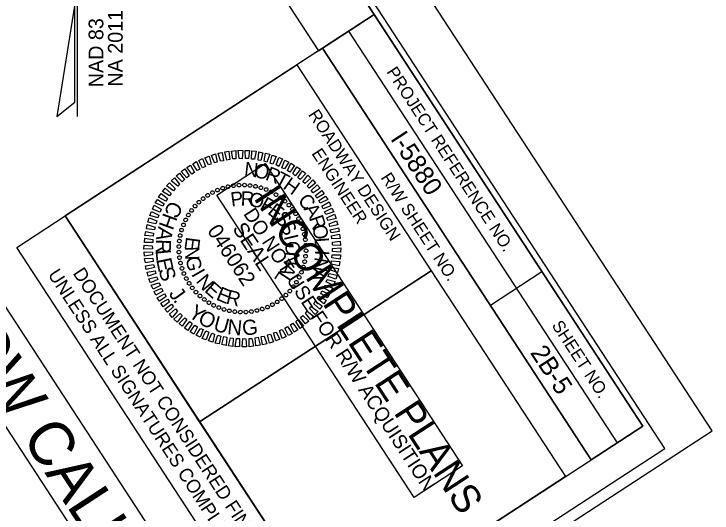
# Model space of a CAD drawing. Extents: x 1639622 to 2864602, y 842655 to 973236.
# Drawn here: x 1641174.9 to 1641458.9, y 843219.7 to 843422.9 of the extents above; entities that cross this region are included whole.
import ezdxf

# ---------------------------------------------------------------- set-up
doc = ezdxf.new("R2010")
doc.units = 0
for name, color, linetype in [('Default', 7, 'Continuous'), ('Old_Level_2', 7, 'Continuous'), ('Prop Dimension Text', 7, 'Continuous'), ('Prop DSN White Annotation Label', 7, 'Continuous'), ('Sheet Data Field CELL', 7, 'Continuous'), ('Sheet North Arrow CELL', 7, 'Continuous'), ('Sheet Plan CELL', 7, 'Continuous'), ('Sheet Plot Border Inside CELL', 7, 'Continuous'), ('Sheet Plot Border Outside CELL', 7, 'Continuous'), ('Sheet Sticker Exception Certification CELL', 7, 'Continuous'), ('Sheet Sticker Incomplete CELL', 7, 'Continuous')]:
    doc.layers.add(name, color=color, linetype=linetype)

msp = doc.modelspace()

# ---------------------------------------------------------------- linework, layer by layer
at = {"layer": 'Old_Level_2'}
for p, q in [((1641266.39, 843353.27), (1641266.39, 843353.27)), ((1641268.65, 843353.24), (1641268.65, 843353.24)), ((1641257.66, 843351.15), (1641257.66, 843351.15)), ((1641259.71, 843351.98), (1641259.71, 843351.98)), ((1641261.91, 843352.6), (1641261.91, 843352.6)), ((1641264.14, 843352.99), (1641264.14, 843352.99)), ((1641270.93, 843353.1), (1641270.93, 843353.1)), ((1641273.12, 843352.72), (1641273.12, 843352.72)), ((1641275.35, 843352.17), (1641275.35, 843352.17)), ((1641277.43, 843351.4), (1641277.43, 843351.4)), ((1641279.52, 843350.45), (1641279.52, 843350.45)), ((1641251.81, 843347.75), (1641251.81, 843347.75)), ((1641253.66, 843349.06), (1641253.66, 843349.06)), ((1641255.62, 843350.21), (1641255.62, 843350.21)), ((1641281.5, 843349.36), (1641281.5, 843349.36)), ((1641283.34, 843348.11), (1641283.34, 843348.11)), ((1641250.14, 843346.24), (1641250.14, 843346.24)), ((1641285.07, 843346.67), (1641285.07, 843346.67)), ((1641286.68, 843345.02), (1641286.68, 843345.02)), ((1641247.05, 843342.9), (1641247.05, 843342.9)), ((1641248.49, 843344.63), (1641248.49, 843344.63)), ((1641288.19, 843343.36), (1641288.19, 843343.36)), ((1641244.72, 843339.08), (1641244.72, 843339.08)), ((1641245.8, 843341.06), (1641245.8, 843341.06)), ((1641289.5, 843341.51), (1641289.5, 843341.51)), ((1641290.65, 843339.54), (1641290.65, 843339.54)), ((1641243.76, 843337), (1641243.76, 843337)), ((1641291.59, 843337.5), (1641291.59, 843337.5)), ((1641242.99, 843334.91), (1641242.99, 843334.91)), ((1641292.42, 843335.45), (1641292.42, 843335.45)), ((1641242.06, 843330.49), (1641242.06, 843330.49)), ((1641242.45, 843332.68), (1641242.45, 843332.68)), ((1641293.04, 843333.25), (1641293.04, 843333.25)), ((1641293.43, 843331.02), (1641293.43, 843331.02)), ((1641241.92, 843328.21), (1641241.92, 843328.21)), ((1641293.71, 843328.77), (1641293.71, 843328.77)), ((1641241.9, 843325.95), (1641241.9, 843325.95)), ((1641267.8, 843327.36), (1641267.8, 843327.36)), ((1641293.68, 843326.51), (1641293.68, 843326.51)), ((1641242.17, 843323.7), (1641242.17, 843323.7)), ((1641293.16, 843322.04), (1641293.16, 843322.04)), ((1641293.54, 843324.24), (1641293.54, 843324.24)), ((1641242.56, 843321.47), (1641242.56, 843321.47)), ((1641243.18, 843319.28), (1641243.18, 843319.28)), ((1641292.61, 843319.81), (1641292.61, 843319.81)), ((1641244.01, 843317.22), (1641244.01, 843317.22)), ((1641291.84, 843317.73), (1641291.84, 843317.73)), ((1641244.96, 843315.18), (1641244.96, 843315.18)), ((1641289.8, 843313.66), (1641289.8, 843313.66)), ((1641290.89, 843315.65), (1641290.89, 843315.65)), ((1641246.1, 843313.22), (1641246.1, 843313.22)), ((1641247.42, 843311.37), (1641247.42, 843311.37)), ((1641288.55, 843311.82), (1641288.55, 843311.82)), ((1641248.92, 843309.7), (1641248.92, 843309.7)), ((1641250.53, 843308.05), (1641250.53, 843308.05)), ((1641285.46, 843308.48), (1641285.46, 843308.48)), ((1641287.11, 843310.09), (1641287.11, 843310.09)), ((1641252.26, 843306.61), (1641252.26, 843306.61)), ((1641254.1, 843305.36), (1641254.1, 843305.36)), ((1641281.95, 843305.66), (1641281.95, 843305.66)), ((1641283.8, 843306.98), (1641283.8, 843306.98)), ((1641256.09, 843304.28), (1641256.09, 843304.28)), ((1641258.17, 843303.32), (1641258.17, 843303.32)), ((1641260.25, 843302.55), (1641260.25, 843302.55)), ((1641273.69, 843302.12), (1641273.69, 843302.12)), ((1641275.89, 843302.74), (1641275.89, 843302.74)), ((1641277.94, 843303.57), (1641277.94, 843303.57)), ((1641279.98, 843304.52), (1641279.98, 843304.52)), ((1641262.48, 843302.01), (1641262.48, 843302.01)), ((1641264.68, 843301.62), (1641264.68, 843301.62)), ((1641266.95, 843301.48), (1641266.95, 843301.48)), ((1641269.21, 843301.46), (1641269.21, 843301.46)), ((1641271.46, 843301.73), (1641271.46, 843301.73))]:
    msp.add_line(p, q, dxfattribs=at)
for points in [[(1641266.46, 843364.1), (1641266.12, 843367.36), (1641267.9, 843367.32), (1641267.69, 843363.94)], [(1641254.02, 843361.4), (1641252.57, 843364.28), (1641254.22, 843364.96), (1641255.15, 843361.67)], [(1641256.45, 843362.23), (1641255.21, 843365.26), (1641256.82, 843365.91), (1641257.57, 843362.5)], [(1641258.93, 843362.98), (1641257.9, 843366.15), (1641259.6, 843366.49), (1641260.15, 843363.12)], [(1641261.39, 843363.4), (1641260.58, 843366.72), (1641262.33, 843366.97), (1641262.62, 843363.61)], [(1641263.93, 843363.88), (1641263.35, 843367.04), (1641265.11, 843367.29), (1641265.09, 843363.92)], [(1641269.04, 843363.98), (1641268.93, 843367.27), (1641270.72, 843367.29), (1641270.23, 843363.97)], [(1641271.53, 843363.79), (1641271.69, 843367.14), (1641273.44, 843366.96), (1641272.7, 843363.72)], [(1641274.17, 843363.4), (1641274.44, 843366.76), (1641276.15, 843366.36), (1641275.31, 843363.18)], [(1641276.62, 843363), (1641277.22, 843366.16), (1641278.94, 843365.83), (1641277.76, 843362.6)], [(1641279.1, 843362.19), (1641279.9, 843365.42), (1641281.58, 843364.87), (1641280.2, 843361.76)], [(1641249.41, 843359.09), (1641247.62, 843361.92), (1641249.09, 843362.79), (1641250.5, 843359.7)], [(1641251.61, 843360.27), (1641250.01, 843363.17), (1641251.58, 843363.99), (1641252.78, 843360.75)], [(1641281.48, 843361.44), (1641282.59, 843364.49), (1641284.15, 843363.93), (1641282.63, 843360.84)], [(1641283.82, 843360.28), (1641285.06, 843363.42), (1641286.64, 843362.56), (1641284.88, 843359.82)], [(1641286.09, 843359.14), (1641287.56, 843362.13), (1641289.05, 843361.21), (1641287.11, 843358.46)], [(1641245.14, 843356.2), (1641242.92, 843358.74), (1641244.32, 843359.81), (1641246.11, 843356.98)], [(1641247.25, 843357.69), (1641245.24, 843360.37), (1641246.69, 843361.36), (1641248.28, 843358.38)], [(1641288.26, 843357.87), (1641289.99, 843360.66), (1641291.37, 843359.72), (1641289.24, 843356.97)], [(1641290.36, 843356.24), (1641292.26, 843358.96), (1641293.54, 843357.89), (1641291.27, 843355.54)], [(1641241.48, 843352.78), (1641238.84, 843354.92), (1641240.12, 843356.16), (1641242.2, 843353.64)], [(1641243.27, 843354.55), (1641240.79, 843356.92), (1641242.15, 843358.03), (1641244.18, 843355.42)], [(1641292.31, 843354.56), (1641294.39, 843357.29), (1641295.67, 843356.04), (1641293.13, 843353.81)], [(1641239.78, 843350.87), (1641236.94, 843352.94), (1641238.18, 843354.15), (1641240.47, 843351.78)], [(1641294.17, 843352.83), (1641296.44, 843355.37), (1641297.52, 843354.05), (1641294.99, 843351.9)], [(1641295.81, 843350.96), (1641298.23, 843353.28), (1641299.38, 843351.94), (1641296.63, 843350.02)], [(1641238.19, 843348.8), (1641235.31, 843350.65), (1641236.32, 843352.02), (1641238.8, 843349.84)], [(1641297.47, 843348.97), (1641300.1, 843351.06), (1641301.02, 843349.62), (1641298.12, 843347.91)], [(1641236.7, 843346.67), (1641233.71, 843348.32), (1641234.7, 843349.81), (1641237.35, 843347.74)], [(1641298.82, 843346.89), (1641301.6, 843348.77), (1641302.51, 843347.33), (1641299.47, 843345.83)], [(1641234.32, 843342.19), (1641231.16, 843343.35), (1641231.89, 843345.03), (1641234.77, 843343.37)], [(1641235.44, 843344.57), (1641232.33, 843345.95), (1641233.28, 843347.4), (1641235.91, 843345.64)], [(1641300.14, 843344.66), (1641303.03, 843346.38), (1641303.73, 843344.79), (1641300.66, 843343.52)], [(1641233.32, 843339.89), (1641230.11, 843340.77), (1641230.8, 843342.42), (1641233.78, 843340.95)], [(1641301.19, 843342.38), (1641304.18, 843343.85), (1641304.92, 843342.3), (1641301.75, 843341.27)], [(1641232.52, 843337.48), (1641229.27, 843338.14), (1641229.81, 843339.82), (1641232.97, 843338.66)], [(1641302.19, 843339.89), (1641305.26, 843341.34), (1641305.9, 843339.66), (1641302.59, 843338.84)], [(1641232, 843334.95), (1641228.75, 843335.42), (1641229.08, 843337.14), (1641232.25, 843336.05)], [(1641303.03, 843337.46), (1641306.11, 843338.61), (1641306.58, 843337), (1641303.34, 843336.36)], [(1641231.54, 843332.39), (1641228.14, 843332.64), (1641228.47, 843334.36), (1641231.64, 843333.64)], [(1641303.56, 843335.02), (1641306.92, 843335.86), (1641307.21, 843334.32), (1641303.93, 843333.83)], [(1641231.32, 843329.87), (1641227.9, 843329.86), (1641228.09, 843331.61), (1641231.37, 843331.09)], [(1641304.05, 843332.55), (1641307.3, 843333.19), (1641307.59, 843331.46), (1641304.22, 843331.29)], [(1641231.23, 843327.25), (1641227.74, 843327.07), (1641227.88, 843328.79), (1641231.1, 843328.54)], [(1641304.38, 843327.47), (1641307.87, 843327.65), (1641307.72, 843325.93), (1641304.5, 843326.18)], [(1641304.4, 843329.92), (1641307.62, 843330.41), (1641307.76, 843328.64), (1641304.44, 843328.76)], [(1641231.2, 843324.81), (1641227.99, 843324.31), (1641227.84, 843326.08), (1641231.16, 843325.97)], [(1641304.28, 843324.85), (1641307.7, 843324.86), (1641307.51, 843323.11), (1641304.23, 843323.63)], [(1641231.55, 843322.18), (1641228.31, 843321.54), (1641228.01, 843323.27), (1641231.38, 843323.44)], [(1641304.06, 843322.33), (1641307.47, 843322.08), (1641307.14, 843320.36), (1641303.97, 843321.08)], [(1641232.04, 843319.71), (1641228.69, 843318.86), (1641228.39, 843320.41), (1641231.67, 843320.89)], [(1641303.6, 843319.78), (1641306.86, 843319.3), (1641306.53, 843317.58), (1641303.36, 843318.67)], [(1641232.58, 843317.26), (1641229.49, 843316.11), (1641229.02, 843317.72), (1641232.27, 843318.36)], [(1641303.08, 843317.24), (1641306.33, 843316.58), (1641305.79, 843314.9), (1641302.63, 843316.06)], [(1641233.41, 843314.84), (1641230.34, 843313.38), (1641229.7, 843315.07), (1641233.02, 843315.88)], [(1641234.42, 843312.34), (1641231.42, 843310.87), (1641230.68, 843312.43), (1641233.85, 843313.45)], [(1641302.28, 843314.83), (1641305.5, 843313.95), (1641304.81, 843312.3), (1641301.82, 843313.77)], [(1641235.46, 843310.06), (1641232.57, 843308.35), (1641231.87, 843309.93), (1641234.94, 843311.2)], [(1641301.28, 843312.53), (1641304.44, 843311.37), (1641303.71, 843309.69), (1641300.84, 843311.36)], [(1641236.78, 843307.84), (1641234.01, 843305.95), (1641233.09, 843307.39), (1641236.13, 843308.89)], [(1641298.9, 843308.05), (1641301.89, 843306.4), (1641300.9, 843304.92), (1641298.25, 843306.99)], [(1641300.16, 843310.15), (1641303.27, 843308.77), (1641302.33, 843307.32), (1641299.69, 843309.09)], [(1641238.13, 843305.76), (1641235.5, 843303.66), (1641234.59, 843305.1), (1641237.48, 843306.81)], [(1641297.41, 843305.92), (1641300.29, 843304.07), (1641299.28, 843302.7), (1641296.81, 843304.89)], [(1641239.79, 843303.77), (1641237.38, 843301.44), (1641236.22, 843302.78), (1641238.97, 843304.7)], [(1641241.44, 843301.89), (1641239.17, 843299.35), (1641238.08, 843300.68), (1641240.61, 843302.83)], [(1641295.83, 843303.85), (1641298.66, 843301.78), (1641297.43, 843300.57), (1641295.13, 843302.94)], [(1641243.29, 843300.16), (1641241.21, 843297.44), (1641239.93, 843298.69), (1641242.47, 843300.91)], [(1641292.33, 843300.17), (1641294.81, 843297.8), (1641293.45, 843296.69), (1641291.43, 843299.31)], [(1641294.12, 843301.95), (1641296.76, 843299.81), (1641295.48, 843298.57), (1641293.4, 843301.08)], [(1641245.24, 843298.48), (1641243.34, 843295.77), (1641242.06, 843296.83), (1641244.33, 843299.18)], [(1641247.34, 843296.85), (1641245.62, 843294.07), (1641244.24, 843295), (1641246.36, 843297.75)], [(1641288.35, 843297.04), (1641290.36, 843294.35), (1641288.91, 843293.36), (1641287.33, 843296.34)], [(1641290.46, 843298.53), (1641292.68, 843295.98), (1641291.29, 843294.91), (1641289.49, 843297.75)], [(1641249.51, 843295.58), (1641248.05, 843292.6), (1641246.55, 843293.51), (1641248.49, 843296.26)], [(1641251.78, 843294.44), (1641250.55, 843291.3), (1641248.97, 843292.16), (1641250.72, 843294.91)], [(1641254.12, 843293.29), (1641253.02, 843290.23), (1641251.45, 843290.79), (1641252.97, 843293.88)], [(1641283.99, 843294.46), (1641285.59, 843291.55), (1641284.02, 843290.74), (1641282.82, 843293.98)], [(1641286.19, 843295.63), (1641287.98, 843292.8), (1641286.52, 843291.93), (1641285.1, 843295.02)], [(1641256.5, 843292.53), (1641255.7, 843289.31), (1641254.02, 843289.85), (1641255.4, 843292.97)], [(1641258.99, 843291.72), (1641258.38, 843288.57), (1641256.66, 843288.9), (1641257.84, 843292.13)], [(1641261.44, 843291.32), (1641261.16, 843287.96), (1641259.45, 843288.36), (1641260.29, 843291.54)], [(1641264.07, 843290.93), (1641263.91, 843287.58), (1641262.16, 843287.77), (1641262.9, 843291.01)], [(1641266.56, 843290.75), (1641266.67, 843287.46), (1641264.89, 843287.43), (1641265.38, 843290.75)], [(1641269.14, 843290.62), (1641269.48, 843287.36), (1641267.7, 843287.41), (1641267.91, 843290.79)], [(1641271.67, 843290.84), (1641272.25, 843287.69), (1641270.49, 843287.43), (1641270.51, 843290.81)], [(1641274.21, 843291.32), (1641275.03, 843288.01), (1641273.27, 843287.75), (1641272.99, 843291.11)], [(1641276.67, 843291.74), (1641277.7, 843288.57), (1641276, 843288.23), (1641275.46, 843291.6)], [(1641279.16, 843292.49), (1641280.4, 843289.46), (1641278.78, 843288.81), (1641278.03, 843292.22)], [(1641281.58, 843293.32), (1641283.04, 843290.44), (1641281.38, 843289.76), (1641280.45, 843293.06)]]:
    msp.add_lwpolyline(points, close=True, dxfattribs=at)
for centre, major_axis in [((1641261.92, 843352.56), (-0.169, 0.724)), ((1641264.14, 843352.98), (-0.105, 0.735)), ((1641266.39, 843353.2), (-0.041, 0.742)), ((1641268.65, 843353.23), (0.024, 0.743)), ((1641270.9, 843353.05), (0.089, 0.738)), ((1641273.13, 843352.69), (0.153, 0.727)), ((1641255.6, 843350.18), (-0.35, 0.655)), ((1641257.64, 843351.16), (-0.292, 0.683)), ((1641259.75, 843351.96), (-0.231, 0.706)), ((1641275.31, 843352.13), (0.216, 0.711)), ((1641277.44, 843351.38), (0.277, 0.689)), ((1641279.5, 843350.45), (0.336, 0.663)), ((1641251.82, 843347.72), (-0.459, 0.584)), ((1641253.66, 843349.03), (-0.406, 0.622)), ((1641281.47, 843349.34), (0.392, 0.631)), ((1641283.33, 843348.06), (0.446, 0.594)), ((1641248.53, 843344.64), (-0.553, 0.496)), ((1641250.11, 843346.25), (-0.508, 0.542)), ((1641285.08, 843346.63), (0.496, 0.553)), ((1641286.69, 843345.05), (0.542, 0.508)), ((1641245.82, 843341.03), (-0.631, 0.392)), ((1641247.1, 843342.89), (-0.594, 0.446)), ((1641288.16, 843343.34), (0.584, 0.459)), ((1641289.47, 843341.5), (0.622, 0.406)), ((1641244.72, 843339.06), (-0.663, 0.336)), ((1641290.62, 843339.56), (0.655, 0.35)), ((1641243.78, 843337), (-0.689, 0.277)), ((1641291.6, 843337.53), (0.683, 0.292)), ((1641292.4, 843335.41), (0.706, 0.231)), ((1641242.48, 843332.69), (-0.727, 0.153)), ((1641243.04, 843334.87), (-0.711, 0.216)), ((1641293, 843333.24), (0.724, 0.169)), ((1641242.11, 843330.46), (-0.738, 0.089)), ((1641293.42, 843331.02), (0.735, 0.105)), ((1641241.94, 843328.21), (-0.743, 0.024)), ((1641293.64, 843328.77), (0.742, 0.041)), ((1641241.96, 843325.95), (-0.742, -0.041)), ((1641293.49, 843324.26), (0.738, -0.089)), ((1641293.67, 843326.52), (0.743, -0.024)), ((1641242.18, 843323.7), (-0.735, -0.105)), ((1641242.6, 843321.48), (-0.724, -0.169)), ((1641293.13, 843322.04), (0.727, -0.153)), ((1641243.21, 843319.31), (-0.706, -0.231)), ((1641292.57, 843319.85), (0.711, -0.216)), ((1641244, 843317.2), (-0.683, -0.292)), ((1641290.89, 843315.66), (0.663, -0.336)), ((1641291.82, 843317.72), (0.689, -0.277)), ((1641244.98, 843315.16), (-0.655, -0.35)), ((1641246.13, 843313.22), (-0.622, -0.406)), ((1641289.78, 843313.7), (0.631, -0.392)), ((1641247.44, 843311.38), (-0.584, -0.459)), ((1641287.07, 843310.09), (0.553, -0.496)), ((1641288.5, 843311.83), (0.594, -0.446)), ((1641248.91, 843309.67), (-0.542, -0.508)), ((1641250.53, 843308.09), (-0.496, -0.553)), ((1641283.78, 843307), (0.459, -0.584)), ((1641285.49, 843308.47), (0.508, -0.542)), ((1641252.27, 843306.66), (-0.446, -0.594)), ((1641254.14, 843305.38), (-0.392, -0.631)), ((1641256.1, 843304.28), (-0.336, -0.663)), ((1641280, 843304.54), (0.35, -0.655)), ((1641281.94, 843305.69), (0.406, -0.622)), ((1641258.16, 843303.35), (-0.277, -0.689)), ((1641260.29, 843302.6), (-0.216, -0.711)), ((1641262.48, 843302.04), (-0.153, -0.727)), ((1641264.7, 843301.67), (-0.089, -0.738)), ((1641266.95, 843301.5), (-0.024, -0.743)), ((1641269.21, 843301.52), (0.041, -0.742)), ((1641271.46, 843301.74), (0.105, -0.735)), ((1641273.68, 843302.16), (0.169, -0.724)), ((1641275.85, 843302.77), (0.231, -0.706)), ((1641277.97, 843303.56), (0.292, -0.683))]:
    msp.add_ellipse(centre, major_axis=major_axis, ratio=0.999708, dxfattribs=at)
at = {"layer": 'Prop Dimension Text'}
msp.add_lwpolyline([(1641216.75, 843533.53), (1641298.74, 843407.89), (1641321.42, 843422.68), (1641239.43, 843548.33)], close=True, dxfattribs=at)
at = {"layer": 'Prop DSN White Annotation Label'}
msp.add_lwpolyline([(1641161.53, 843318.56), (1641268.96, 843153.93), (1641246.78, 843139.46), (1641139.35, 843304.09)], close=True, dxfattribs=at)
at = {"layer": 'Sheet North Arrow CELL'}
msp.add_line((1641200.65, 843381.18), (1641200.65, 843511.18), dxfattribs=at)
msp.add_lwpolyline([(1641199.59, 843426.98), (1641192.23, 843381.18), (1641199.59, 843386.98)], close=True, dxfattribs=at)
at = {"layer": 'Sheet Plan CELL'}
for p, q in [((1641310.9, 843415.83), (1641420.21, 843248.29)), ((1641300.41, 843408.97), (1641289.95, 843402.15)), ((1641300.41, 843408.97), (1641409.74, 843241.46)), ((1641300.41, 843408.97), (1641409.74, 843241.46)), ((1641344.62, 843318.36), (1641250.45, 843256.89)), ((1641389.67, 843317.95), (1641368.76, 843304.24))]:
    msp.add_line(p, q, dxfattribs=at)
for points in [[(1641430.74, 843255.12), (1640611, 844511.36), (1639731.66, 843937.55), (1640551.38, 842681.33)], [(1639731.66, 843937.55), (1640610.97, 844511.36), (1641321.42, 843422.68), (1641195.75, 843340.66), (1641305.06, 843173.13), (1640551.38, 842681.33)], [(1641321.42, 843422.68), (1641430.74, 843255.12), (1641409.74, 843241.46), (1641300.41, 843408.97)], [(1641289.95, 843402.15), (1641344.62, 843318.36), (1641250.4, 843256.87), (1641195.75, 843340.66)], [(1641344.62, 843318.36), (1641399.27, 843234.63), (1641305.06, 843173.13), (1641250.4, 843256.87)]]:
    msp.add_lwpolyline(points, close=True, dxfattribs=at)
at = {"layer": 'Sheet Plot Border Inside CELL'}
msp.add_lwpolyline([(1639645.67, 844064.72), (1640556.11, 842669.51), (1641439.64, 843246.03), (1640529.21, 844641.26)], close=True, dxfattribs=at)
at = {"layer": 'Sheet Plot Border Outside CELL'}
msp.add_lwpolyline([(1639621.82, 844064.68), (1640541.82, 842654.79), (1641458.85, 843253.19), (1640538.85, 844663.07)], close=True, dxfattribs=at)
msp.add_lwpolyline([(1639621.82, 844064.68), (1640541.82, 842654.79), (1641458.85, 843253.19), (1640538.85, 844663.07)], close=True, dxfattribs=at)
at = {"layer": 'Sheet Sticker Exception Certification CELL'}
for p, q in [((1641176.07, 843327.82), (1641195.75, 843340.66)), ((1641176.07, 843327.82), (1641195.75, 843340.66)), ((1641195.75, 843340.66), (1641305.07, 843173.14)), ((1641195.75, 843340.66), (1641305.07, 843173.14)), ((1641285.39, 843160.3), (1641176.07, 843327.82)), ((1641285.39, 843160.3), (1641176.07, 843327.82))]:
    msp.add_line(p, q, dxfattribs=at)
at = {"layer": 'Sheet Sticker Incomplete CELL'}
msp.add_lwpolyline([(1641257.35, 843349.17), (1641277.03, 843362.02), (1641357.36, 843238.91), (1641337.68, 843226.06)], close=True, dxfattribs=at)

# ---------------------------------------------------------------- texts
at = {"layer": 'Default'}
for s, rotation, p in [('C', 240.3258, (1641238.6, 843347.33)), ('H', 249.7695, (1641235.71, 843342.26)), ('A', 259.6093, (1641233.64, 843336.56)), ('R', 268.322, (1641232.63, 843331.28)), ('L', 275.6942, (1641232.42, 843326.74)), ('E', 281.8784, (1641232.69, 843322.93)), ('S', 288.885, (1641233.49, 843318.68)), ('J', 306.158, (1641237.61, 843308.89)), ('.', 311.3399, (1641239.4, 843306.24)), ('Y', 325.3685, (1641245.36, 843299.98)), ('O', 333.1672, (1641249.28, 843297.19)), ('U', 344.5606, (1641255.61, 843294.13)), ('N', 354.3548, (1641261.43, 843292.54)), ('G', 4.9257, (1641267.93, 843291.97))]:
    msp.add_text(s, height=6.19, rotation=rotation, dxfattribs=at).set_placement(p)
at = {"layer": 'Old_Level_2'}
for s, height, rotation, p in [('N', 5.82, 353.5494, (1641268.32, 843356.94)), ('O', 5.82, 346.3476, (1641272.13, 843356.66)), ('R', 5.82, 339.1464, (1641276.77, 843355.51)), ('T', 5.82, 331.9457, (1641280.62, 843353.88)), ('H', 5.82, 324.7454, (1641283.91, 843352.05)), ('P', 5.82, 7.5248, (1641263.35, 843344.41)), ('R', 5.82, 358.1656, (1641267.01, 843344.9)), ('O', 5.82, 348.8071, (1641270.12, 843344.82)), ('F', 5.82, 330.0929, (1641274.55, 843343.71)), ('C', 5.82, 310.3458, (1641290.02, 843346.72)), ('E', 5.82, 320.737, (1641277.68, 843341.85)), ('A', 5.82, 303.1462, (1641292.56, 843343.52)), ('S', 5.82, 311.3815, (1641280.57, 843339.51)), ('R', 5.82, 288.747, (1641294.82, 843339.82)), ('046062', 6.191, 303.1259, (1641253.24, 843334.65)), ('SEAL', 6.189, 303.1259, (1641263.53, 843335.5)), ('S', 5.82, 302.0263, (1641282.7, 843336.46)), ('O', 5.82, 281.5471, (1641296.12, 843336.52)), ('E', 5.82, 262.4028, (1641244.94, 843332.31)), ('I', 5.82, 283.3155, (1641284.59, 843332.38)), ('L', 5.82, 274.3468, (1641297.09, 843331.69)), ('N', 5.82, 271.7599, (1641244.37, 843328.18)), ('O', 5.82, 273.9594, (1641285.15, 843330.27)), ('N', 5.82, 264.6025, (1641285.38, 843326.25)), ('I', 5.82, 267.146, (1641297.38, 843326.84)), ('G', 5.82, 281.1161, (1641244.65, 843323.64)), ('A', 5.82, 245.8862, (1641284.81, 843322.31)), ('N', 5.82, 259.9448, (1641297.3, 843324.11)), ('I', 5.82, 299.8271, (1641246.82, 843316.94)), ('A', 5.82, 252.7431, (1641296.49, 843319.88)), ('N', 5.82, 309.1823, (1641248.63, 843313.99)), ('L', 5.82, 236.5268, (1641282.99, 843318.65)), ('E', 5.82, 318.5377, (1641252.01, 843310.11)), ('E', 5.82, 337.25, (1641256.74, 843306.71)), ('R', 5.82, 346.6073, (1641260.8, 843305.04))]:
    msp.add_text(s, height=height, rotation=rotation, dxfattribs=at).set_placement(p)
at = {"layer": 'Prop DSN White Annotation Label'}
msp.add_text('ROW CALLOUTS', height=18, rotation=303.1259, dxfattribs=at).set_placement((1641141.89, 843305.6))
at = {"layer": 'Sheet Data Field CELL'}
for s, p in [('I-5880', (1641327.79, 843372.07)), ('2B-5', (1641384.68, 843284.99))]:
    msp.add_text(s, height=7.5, rotation=303.1259, dxfattribs=at).set_placement(p)
at = {"layer": 'Sheet North Arrow CELL'}
for s, p in [('NA 2011', (1641219.09, 843393.29)), ('NAD 83', (1641211.22, 843393.05))]:
    msp.add_text(s, height=6, rotation=90, dxfattribs=at).set_placement(p)
at = {"layer": 'Sheet Plan CELL'}
for s, height, p in [('PROJECT REFERENCE NO.', 5.0001, (1641326.24, 843399.32)), ('ROADWAY DESIGN', 5.0001, (1641294.42, 843381.93)), ('ENGINEER', 5, (1641295.75, 843366.1)), ('R/W SHEET NO.', 5.0001, (1641323.86, 843356.22)), ('SHEET NO.', 5, (1641393.45, 843296.12))]:
    msp.add_text(s, height=height, rotation=303.1259, dxfattribs=at).set_placement(p)
at = {"layer": 'Sheet Sticker Exception Certification CELL'}
for s, p in [('UNLESS ALL SIGNATURES COMPLETED', (1641188.46, 843316.8)), ('UNLESS ALL SIGNATURES COMPLETED', (1641188.46, 843316.8)), ('DOCUMENT NOT CONSIDERED FINAL', (1641198.6, 843317.37)), ('DOCUMENT NOT CONSIDERED FINAL', (1641198.6, 843317.37))]:
    msp.add_text(s, height=5.5, rotation=303.1259, dxfattribs=at).set_placement(p)
at = {"layer": 'Sheet Sticker Incomplete CELL'}
for s, height, p in [('INCOMPLETE PLANS', 11.52, (1641272.04, 843348.07)), ('DO NOT USE FOR R/W ACQUISITION', 5.76, (1641267.99, 843341.55))]:
    msp.add_text(s, height=height, rotation=303.1259, dxfattribs=at).set_placement(p)

doc.saveas('drawing.dxf')
